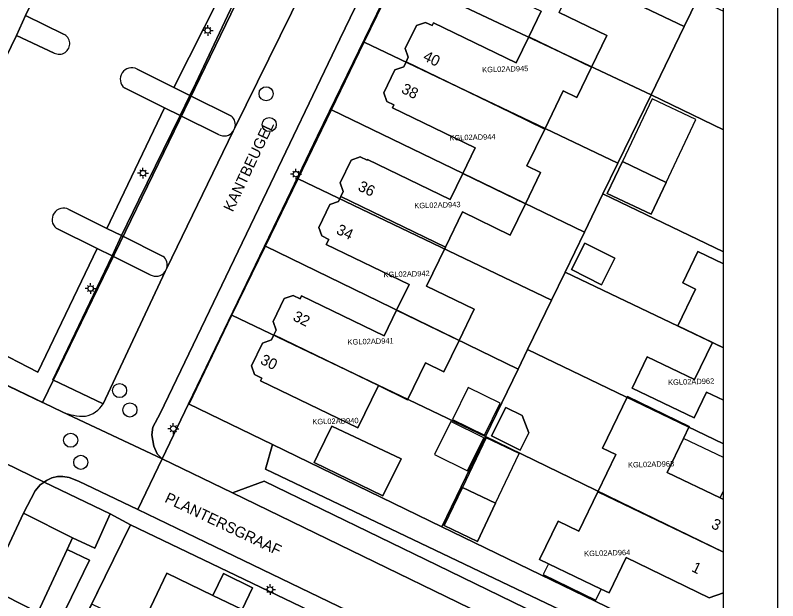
# Model space of a CAD drawing. Extents: x 124901 to 125496, y 515369 to 515789.
# Drawn here: x 125425.6 to 125495.9, y 515463 to 515517 of the extents above; entities that cross this region are included whole.
import ezdxf

# ---------------------------------------------------------------- set-up
doc = ezdxf.new("R2010")
doc.units = 0
for name, color, linetype in [('Alg Kaders', 7, 'Continuous'), ('Gebouw', 7, 'Continuous'), ('Lichtmast', 7, 'Continuous'), ('Luifel', 7, 'Continuous'), ('Onbegroeid terrein', 7, 'Continuous'), ('Parkeren', 7, 'Continuous'), ('Perceelnummers', 7, 'Continuous'), ('Perceelsgrenzen', 7, 'Continuous'), ('Putten', 7, 'Continuous'), ('Teksten', 7, 'Continuous'), ('Vegetatie', 7, 'Continuous'), ('Voetpad', 7, 'Continuous'), ('Wegen lokale weg', 7, 'Continuous')]:
    doc.layers.add(name, color=color, linetype=linetype)

msp = doc.modelspace()

# ---------------------------------------------------------------- linework, layer by layer
at = {"layer": 'Alg Kaders'}
for points in [[(125495.925, 515789.043), (124901.425, 515789.043), (124901.425, 515368.543), (125495.925, 515368.543)], [(125490.925, 515784.043), (124906.425, 515784.043), (124906.425, 515373.543), (125490.925, 515373.543)]]:
    msp.add_lwpolyline(points, close=True, dxfattribs=at)
at = {"layer": 'Gebouw'}
for points in [[(125466.616, 515521.375), (125466.483, 515521.1), (125474.117, 515517.407), (125472.966, 515515.027), (125478.748, 515512.228), (125480.167, 515515.158), (125475.77, 515517.287), (125477.402, 515520.659), (125467.751, 515525.33), (125467.536, 515524.879), (125466.727, 515524.591), (125465.705, 515522.475), (125465.982, 515521.681)], [(125464.052, 515516.076), (125463.437, 515516.373), (125462.603, 515516.082), (125461.581, 515513.966), (125461.863, 515513.175), (125461.648, 515512.723), (125471.299, 515508.051), (125474.434, 515506.533), (125476.135, 515510.047), (125477.397, 515509.436), (125478.748, 515512.228), (125472.966, 515515.027), (125471.814, 515512.647), (125464.18, 515516.34)], [(125460.624, 515511.984), (125459.602, 515509.868), (125459.879, 515509.074), (125460.521, 515508.763), (125460.389, 515508.49), (125468.023, 515504.803), (125466.874, 515502.423), (125472.655, 515499.642), (125474.054, 515502.532), (125472.793, 515503.142), (125474.434, 515506.533), (125471.299, 515508.051), (125461.648, 515512.723), (125461.433, 515512.272)], [(125466.859, 515498.881), (125471.256, 515496.752), (125472.655, 515499.642), (125466.874, 515502.423), (125465.724, 515500.043), (125458.09, 515503.73), (125458.056, 515503.66), (125457.431, 515503.962), (125456.597, 515503.671), (125455.575, 515501.555), (125455.857, 515500.764), (125455.642, 515500.312), (125465.291, 515495.642)], [(125485.644, 515501.614), (125481.598, 515503.528), (125480.209, 515500.592), (125484.255, 515498.678)], [(125455.642, 515500.312), (125455.427, 515499.861), (125454.618, 515499.573), (125453.596, 515497.457), (125453.873, 515496.663), (125454.523, 515496.349), (125454.299, 515495.886), (125461.927, 515492.199), (125460.778, 515489.821), (125466.548, 515487.027), (125467.946, 515489.914), (125463.549, 515492.043), (125465.291, 515495.642)], [(125478.152, 515496.013), (125476.911, 515493.576), (125479.675, 515492.169), (125480.916, 515494.606)], [(125459.628, 515487.443), (125452, 515491.13), (125451.876, 515490.872), (125451.242, 515491.178), (125450.408, 515490.887), (125449.386, 515488.771), (125449.668, 515487.98), (125449.453, 515487.528), (125459.102, 515482.857), (125461.782, 515481.56), (125463.431, 515484.966), (125465.148, 515484.135), (125466.548, 515487.027), (125460.778, 515489.821)], [(125447.684, 515483.879), (125448.349, 515483.558), (125448.22, 515483.29), (125457.21, 515478.95), (125459.102, 515482.857), (125449.453, 515487.528), (125449.238, 515487.077), (125448.429, 515486.789), (125447.407, 515484.673)], [(125472.351, 515480.097), (125470.843, 515480.851), (125469.525, 515478.214), (125472.162, 515476.896), (125472.964, 515478.501)], [(125453.521, 515476.477), (125453.17, 515475.76), (125459.51, 515472.69), (125461.189, 515476.094), (125454.809, 515479.105)], [(125466.853, 515473.459), (125465.176, 515469.949), (125468.229, 515468.489), (125469.907, 515472)], [(125445.38, 515456.564), (125447.8, 515461.59), (125446.54, 515462.199), (125443.839, 515463.505), (125439.61, 515465.55), (125437.183, 515460.514)], [(125446.54, 515462.199), (125447.509, 515464.202), (125444.808, 515465.508), (125443.839, 515463.505)]]:
    msp.add_lwpolyline(points, close=True, dxfattribs=at)
for points in [[(125490.925, 515494.106), (125488.55, 515495.245), (125487.159, 515492.341), (125488.347, 515491.771), (125486.715, 515488.379), (125489.902, 515486.846), (125490.925, 515486.354)], [(125490.925, 515486.354), (125489.902, 515486.846), (125488.264, 515483.428), (125483.891, 515485.525), (125482.503, 515482.63), (125488.22, 515479.89), (125489.362, 515482.266), (125490.925, 515481.515)], [(125490.925, 515472.338), (125490.602, 515472.494), (125485.728, 515474.844), (125487.245, 515477.99), (125487.771, 515479.082), (125482.062, 515481.85), (125479.765, 515477.085), (125480.997, 515476.491), (125479.344, 515473.063), (125490.925, 515467.495)], [(125490.925, 515467.495), (125479.344, 515473.063), (125477.588, 515469.419), (125475.666, 515470.345), (125473.964, 515466.814), (125474.786, 515466.418), (125479.637, 515464.078), (125480.368, 515463.726), (125481.942, 515466.991), (125489.61, 515463.28), (125490.925, 515463.739)]]:
    msp.add_lwpolyline(points, dxfattribs=at)
at = {"layer": 'Lichtmast'}
for p, q in [((125443.363, 515515.931), (125443.363, 515516.131)), ((125443.063, 515515.632), (125442.863, 515515.631)), ((125443.151, 515515.419), (125443.079, 515515.348)), ((125443.151, 515515.843), (125443.081, 515515.914)), ((125443.363, 515515.331), (125443.363, 515515.131)), ((125443.575, 515515.843), (125443.646, 515515.915)), ((125443.575, 515515.419), (125443.645, 515515.348)), ((125443.663, 515515.631), (125443.863, 515515.631)), ((125437.186, 515502.679), (125437.116, 515502.75)), ((125437.398, 515502.767), (125437.398, 515502.967)), ((125437.61, 515502.679), (125437.681, 515502.751)), ((125451.286, 515502.581), (125451.216, 515502.652)), ((125451.498, 515502.669), (125451.498, 515502.869)), ((125451.71, 515502.581), (125451.781, 515502.653)), ((125437.098, 515502.468), (125436.898, 515502.467)), ((125437.186, 515502.255), (125437.114, 515502.184)), ((125437.398, 515502.167), (125437.398, 515501.967)), ((125437.61, 515502.255), (125437.68, 515502.184)), ((125437.698, 515502.467), (125437.898, 515502.467)), ((125451.198, 515502.37), (125450.998, 515502.369)), ((125451.286, 515502.157), (125451.214, 515502.086)), ((125451.498, 515502.069), (125451.498, 515501.869)), ((125451.71, 515502.157), (125451.78, 515502.086)), ((125451.798, 515502.369), (125451.998, 515502.369)), ((125432.354, 515492.03), (125432.284, 515492.101)), ((125432.566, 515492.118), (125432.566, 515492.318)), ((125432.778, 515492.03), (125432.849, 515492.102)), ((125432.266, 515491.819), (125432.066, 515491.818)), ((125432.354, 515491.606), (125432.282, 515491.535)), ((125432.566, 515491.518), (125432.566, 515491.318)), ((125432.778, 515491.606), (125432.848, 515491.535)), ((125432.866, 515491.818), (125433.066, 515491.818)), ((125440.195, 515479.183), (125440.195, 515479.383)), ((125439.895, 515478.884), (125439.695, 515478.883)), ((125439.983, 515478.671), (125439.911, 515478.6)), ((125439.983, 515479.095), (125439.913, 515479.166)), ((125440.407, 515479.095), (125440.478, 515479.167)), ((125440.407, 515478.671), (125440.477, 515478.6)), ((125440.495, 515478.883), (125440.695, 515478.883)), ((125440.195, 515478.583), (125440.195, 515478.383)), ((125448.812, 515464.044), (125448.612, 515464.043)), ((125448.9, 515464.255), (125448.83, 515464.326)), ((125449.112, 515464.343), (125449.112, 515464.543)), ((125449.324, 515464.255), (125449.395, 515464.327)), ((125449.412, 515464.043), (125449.612, 515464.043)), ((125448.9, 515463.831), (125448.828, 515463.76)), ((125449.112, 515463.743), (125449.112, 515463.543)), ((125449.324, 515463.831), (125449.394, 515463.76))]:
    msp.add_line(p, q, dxfattribs=at)
for centre in [(125443.363, 515515.631), (125437.398, 515502.467), (125451.498, 515502.369), (125432.566, 515491.818), (125440.195, 515478.883), (125449.112, 515464.043)]:
    msp.add_circle(centre, 0.25, dxfattribs=at)
at = {"layer": 'Luifel'}
for points in [[(125484.338, 515509.319), (125481.598, 515503.528), (125485.644, 515501.614), (125488.384, 515507.405)], [(125465.94, 515479.736), (125468.875, 515478.292), (125470.319, 515481.226), (125467.384, 515482.67)], [(125465.785, 515479.558), (125464.262, 515476.51), (125467.31, 515474.987), (125468.833, 515478.035)], [(125469.042, 515478.039), (125466.853, 515473.459), (125469.907, 515472), (125472.096, 515476.579)], [(125479.15, 515463.07), (125479.637, 515464.078), (125474.786, 515466.418), (125474.301, 515465.417)]]:
    msp.add_lwpolyline(points, close=True, dxfattribs=at)
msp.add_lwpolyline([(125490.925, 515476.216), (125487.245, 515477.99), (125485.728, 515474.844), (125490.602, 515472.494), (125490.925, 515473.164)], dxfattribs=at)
at = {"layer": 'Onbegroeid terrein'}
for points in [[(125490.925, 515572.93), (125486.902, 515574.852), (125481.271, 515563.266), (125474.678, 515549.593), (125462.223, 515523.884), (125453.501, 515505.907), (125450.658, 515500), (125442.003, 515482.019), (125441.598, 515481.177), (125449.353, 515477.41), (125464.945, 515469.835), (125487.213, 515459.032), (125490.925, 515457.212)], [(125430.976, 515530.884), (125416, 515500), (125410.936, 515489.556), (125412.78, 515488.671), (125413.974, 515490.907), (125418.349, 515500), (125419.408, 515502.202), (125420.273, 515503.939), (125425.747, 515515.155), (125426.577, 515517.021), (125435.435, 515535.182), (125449.018, 515530.602), (125450.733, 515534.132)], [(125442.778, 515524.769), (125448.478, 515522.144), (125452.076, 515529.571), (125449.018, 515530.602), (125435.435, 515535.182), (125426.577, 515517.021), (125430.065, 515515.298)], [(125436.845, 515512.058), (125440.231, 515510.372), (125445.899, 515521.606), (125441.755, 515523.591)], [(125475.77, 515517.287), (125480.167, 515515.158), (125478.748, 515512.228), (125477.397, 515509.436), (125476.135, 515510.047), (125474.434, 515506.533), (125472.793, 515503.142), (125474.054, 515502.532), (125472.655, 515499.642), (125471.256, 515496.752), (125466.859, 515498.881), (125465.291, 515495.642), (125463.549, 515492.043), (125467.946, 515489.914), (125466.548, 515487.027), (125465.148, 515484.135), (125463.431, 515484.966), (125461.782, 515481.56), (125459.102, 515482.857), (125457.21, 515478.95), (125448.22, 515483.29), (125448.349, 515483.558), (125447.684, 515483.879), (125447.407, 515484.673), (125448.429, 515486.789), (125449.238, 515487.077), (125449.453, 515487.528), (125449.668, 515487.98), (125449.386, 515488.771), (125450.408, 515490.887), (125451.242, 515491.178), (125451.876, 515490.872), (125452, 515491.13), (125459.628, 515487.443), (125460.778, 515489.821), (125461.927, 515492.199), (125454.299, 515495.886), (125454.523, 515496.349), (125453.873, 515496.663), (125453.596, 515497.457), (125454.618, 515499.573), (125455.427, 515499.861), (125455.642, 515500.312), (125455.857, 515500.764), (125455.575, 515501.555), (125456.597, 515503.671), (125457.431, 515503.962), (125458.056, 515503.66), (125458.09, 515503.73), (125465.724, 515500.043), (125466.874, 515502.423), (125468.023, 515504.803), (125460.389, 515508.49), (125460.521, 515508.763), (125459.879, 515509.074), (125459.602, 515509.868), (125460.624, 515511.984), (125461.433, 515512.272), (125461.648, 515512.723), (125461.863, 515513.175), (125461.581, 515513.966), (125462.603, 515516.082), (125463.437, 515516.373), (125464.052, 515516.076), (125464.18, 515516.34), (125471.814, 515512.647), (125472.966, 515515.027), (125474.117, 515517.407)], [(125429.216, 515513.547), (125425.747, 515515.155), (125420.273, 515503.939), (125423.856, 515502.228)], [(125435.68, 515510.328), (125439.389, 515508.491), (125440.811, 515507.787), (125441.713, 515509.635), (125440.231, 515510.372), (125436.845, 515512.058)], [(125430.56, 515499.11), (125434.061, 515497.367), (125435.322, 515500), (125439.389, 515508.491), (125435.68, 515510.328)], [(125422.944, 515500.536), (125419.408, 515502.202), (125418.349, 515500), (125413.974, 515490.907), (125423.261, 515486.38), (125423.264, 515486.386), (125427.708, 515484.107), (125433.171, 515495.51), (125429.395, 515497.38)], [(125434.061, 515497.367), (125430.56, 515499.11)], [(125429.395, 515497.38), (125433.171, 515495.51), (125434.563, 515494.821), (125435.405, 515496.698), (125434.061, 515497.367)], [(125490.925, 515481.515), (125489.362, 515482.266), (125488.22, 515479.89), (125482.503, 515482.63), (125483.891, 515485.525), (125488.264, 515483.428), (125489.902, 515486.846), (125486.715, 515488.379), (125488.347, 515491.771), (125487.159, 515492.341), (125488.55, 515495.245), (125490.925, 515494.106)], [(125490.925, 515463.739), (125489.61, 515463.28), (125481.942, 515466.991), (125480.368, 515463.726), (125479.637, 515464.078), (125474.786, 515466.418), (125473.964, 515466.814), (125475.666, 515470.345), (125477.588, 515469.419), (125479.344, 515473.063), (125480.997, 515476.491), (125479.765, 515477.085), (125482.062, 515481.85), (125487.771, 515479.082), (125487.245, 515477.99), (125485.728, 515474.844), (125490.602, 515472.494), (125490.925, 515472.338)], [(125457.218, 515459.955), (125436.24, 515470.006), (125427.701, 515452.562)]]:
    msp.add_lwpolyline(points, dxfattribs=at)
for points in [[(125481.598, 515503.528), (125485.644, 515501.614), (125484.255, 515498.678), (125480.209, 515500.592)], [(125478.152, 515496.013), (125480.916, 515494.606), (125479.675, 515492.169), (125476.911, 515493.576)], [(125472.351, 515480.097), (125472.964, 515478.501), (125472.162, 515476.896), (125469.525, 515478.214), (125470.843, 515480.851)], [(125453.17, 515475.76), (125453.521, 515476.477), (125454.809, 515479.105), (125461.189, 515476.094), (125459.51, 515472.69)], [(125469.907, 515472), (125468.229, 515468.489), (125465.176, 515469.949), (125466.853, 515473.459)], [(125447.8, 515461.59), (125445.38, 515456.564), (125443.043, 515451.71), (125440.706, 515446.855), (125438.285, 515441.827), (125430.08, 515445.77), (125432.506, 515450.805), (125434.845, 515455.659), (125437.183, 515460.514), (125439.61, 515465.55), (125443.839, 515463.505), (125444.808, 515465.508), (125447.509, 515464.202), (125446.54, 515462.199)]]:
    msp.add_lwpolyline(points, close=True, dxfattribs=at)
for centre, radius, start, end in [((125429.67, 515514.408), 0.974, 242.19151, 66.07417), ((125436.347, 515511.136), 1.048, 61.60731, 230.47923), ((125436.347, 515511.136), 1.048, 61.60731, 230.47923), ((125430.062, 515498.188), 1.048, 61.64099, 230.44554), ((125430.062, 515498.188), 1.048, 61.64099, 230.44554)]:
    msp.add_arc(centre, radius, start, end, dxfattribs=at)
at = {"layer": 'Parkeren'}
for points in [[(125451.065, 515519.177), (125447.153, 515521.005), (125445.448, 515517.506), (125442.268, 515510.774), (125441.713, 515509.635), (125445.553, 515507.723)], [(125445.872, 515506.632), (125452.147, 515519.408)], [(125444.347, 515506.035), (125440.811, 515507.787), (125437.015, 515500), (125435.405, 515496.698), (125439.268, 515494.775)], [(125439.59, 515493.693), (125445.722, 515506.327)], [(125438.062, 515493.087), (125434.563, 515494.821), (125429.091, 515483.398), (125433.716, 515481.182), (125439.438, 515493.379)]]:
    msp.add_lwpolyline(points, dxfattribs=at)
for points in [[(125479.548, 515456.488), (125478.49, 515459.49), (125464.507, 515466.302), (125448.564, 515474.053), (125445.638, 515472.977)], [(125430.901, 515468.821), (125426.393, 515471.074), (125423.161, 515464.229), (125427.7, 515461.925), (125430.399, 515467.739)]]:
    msp.add_lwpolyline(points, close=True, dxfattribs=at)
for centre, radius, start, end in [((125444.875, 515506.933), 1.041, 343.22614, 49.37089), ((125444.875, 515506.933), 1.041, 239.54662, 324.43223), ((125438.592, 515493.985), 1.04, 343.70766, 49.43804), ((125438.591, 515493.984), 1.041, 239.49949, 324.46243)]:
    msp.add_arc(centre, radius, start, end, dxfattribs=at)
at = {"layer": 'Perceelsgrenzen'}
for points in [[(125490.925, 515457.207), (125464.945, 515469.835), (125441.643, 515481.155), (125445.603, 515489.346), (125448.69, 515495.731), (125451.695, 515501.947), (125454.769, 515508.305), (125457.788, 515514.55), (125460.796, 515520.771), (125463.885, 515527.161), (125466.909, 515533.415), (125469.979, 515539.764), (125473.42, 515546.88), (125473.912, 515547.898), (125486.939, 515574.835), (125490.925, 515572.929)], [(125371.042, 515509.03), (125394.211, 515497.789), (125397.391, 515499.007), (125406.255, 515494.775), (125407.292, 515491.306), (125428.143, 515481.293), (125438.838, 515503.36), (125447.882, 515522.111), (125445.448, 515523.259), (125464.025, 515561.476)], [(125464.025, 515561.476), (125445.448, 515523.259), (125447.882, 515522.111), (125438.838, 515503.36), (125428.143, 515481.293), (125407.292, 515491.306), (125406.255, 515494.775), (125397.391, 515499.007), (125394.211, 515497.789), (125371.042, 515509.03)], [(125490.925, 515506.445), (125484.24, 515509.693), (125487.285, 515515.984), (125488.528, 515518.553), (125490.925, 515517.398)], [(125490.925, 515495.215), (125479.81, 515500.543), (125481.182, 515503.377), (125484.24, 515509.693), (125490.925, 515506.445)], [(125490.925, 515486.344), (125476.319, 515493.331), (125478.103, 515497.016), (125479.81, 515500.543), (125490.925, 515495.215)], [(125490.925, 515477.49), (125472.866, 515486.198), (125475.068, 515490.747), (125476.319, 515493.331), (125490.925, 515486.344)], [(125490.925, 515467.499), (125482.504, 515471.59), (125468.977, 515478.164), (125471.988, 515484.385), (125472.866, 515486.198), (125490.925, 515477.49)], [(125490.925, 515457.207), (125464.945, 515469.835), (125468.977, 515478.164), (125482.504, 515471.59), (125490.925, 515467.499)]]:
    msp.add_lwpolyline(points, dxfattribs=at)
for points in [[(125463.885, 515527.161), (125466.909, 515533.415), (125490.333, 515522.281), (125488.528, 515518.553), (125487.285, 515515.984)], [(125460.796, 515520.771), (125463.885, 515527.161), (125487.285, 515515.984), (125484.24, 515509.693)], [(125457.788, 515514.55), (125460.796, 515520.771), (125484.24, 515509.693), (125481.182, 515503.377)], [(125454.769, 515508.305), (125457.788, 515514.55), (125481.182, 515503.377), (125479.81, 515500.543), (125478.103, 515497.016)], [(125451.695, 515501.947), (125454.769, 515508.305), (125478.103, 515497.016), (125476.319, 515493.331), (125475.068, 515490.747)], [(125451.695, 515501.947), (125475.068, 515490.747), (125472.866, 515486.198), (125471.988, 515484.385), (125448.69, 515495.731)], [(125445.603, 515489.346), (125448.69, 515495.731), (125471.988, 515484.385), (125468.977, 515478.164)], [(125464.945, 515469.835), (125441.643, 515481.155), (125445.603, 515489.346), (125468.977, 515478.164)], [(125422.352, 515412.077), (125416.323, 515429.095), (125425.515, 515447.977), (125427.947, 515452.971), (125430.307, 515457.819), (125432.68, 515462.693), (125436.24, 515470.006), (125458.379, 515459.386), (125466.196, 515455.636), (125473.945, 515451.919), (125481.696, 515448.201), (125490.418, 515444.017), (125486.87, 515436.73), (125484.12, 515431.04), (125477.96, 515418.22), (125473.069, 515420.579), (125472.365, 515419.12), (125460.158, 515393.807), (125453.949, 515396.807)], [(125458.379, 515459.386), (125454.836, 515452.035), (125432.68, 515462.693), (125436.24, 515470.006)]]:
    msp.add_lwpolyline(points, close=True, dxfattribs=at)
at = {"layer": 'Putten'}
for centre in [(125448.75, 515509.79), (125449.04, 515506.94), (125435.24, 515482.4), (125436.19, 515480.61), (125430.73, 515477.82), (125431.66, 515475.78)]:
    msp.add_circle(centre, 0.65, dxfattribs=at)
at = {"layer": 'Vegetatie'}
for points in [[(125441.755, 515523.591), (125445.899, 515521.606), (125440.231, 515510.372), (125441.713, 515509.635), (125442.268, 515510.774), (125445.448, 515517.506)], [(125426.577, 515517.021), (125425.747, 515515.155), (125429.216, 515513.547)], [(125430.065, 515515.298), (125426.577, 515517.021)], [(125433.716, 515481.182), (125429.091, 515483.398), (125434.563, 515494.821), (125433.171, 515495.51), (125427.708, 515484.107), (125423.264, 515486.386), (125423.261, 515486.38), (125413.974, 515490.907), (125412.78, 515488.671), (125429.95, 515480.425)], [(125490.925, 515457.212), (125487.213, 515459.032), (125485.862, 515455.269), (125481.275, 515457.151), (125479.981, 515460.21), (125448.694, 515475.147), (125449.353, 515477.41), (125441.598, 515481.177), (125439.157, 515476.105), (125445.638, 515472.977), (125448.564, 515474.053), (125464.507, 515466.302), (125478.49, 515459.49), (125479.548, 515456.488), (125489.604, 515451.765), (125490.925, 515454.494)]]:
    msp.add_lwpolyline(points, dxfattribs=at)
for points in [[(125434.061, 515497.367), (125435.405, 515496.698), (125437.015, 515500), (125440.811, 515507.787), (125439.389, 515508.491), (125435.322, 515500)], [(125481.275, 515457.151), (125485.862, 515455.269), (125487.213, 515459.032), (125464.945, 515469.835), (125449.353, 515477.41), (125448.694, 515475.147), (125479.981, 515460.21)], [(125426.393, 515471.074), (125430.901, 515468.821), (125432.945, 515467.846), (125434.362, 515471.036), (125428.28, 515473.943), (125427.913, 515473.706), (125427.454, 515473.161)], [(125421.631, 515460.932), (125426.14, 515458.647), (125426.06, 515458.488), (125428.014, 515457.588), (125432.457, 515466.767), (125430.399, 515467.739), (125427.7, 515461.925), (125423.161, 515464.229)]]:
    msp.add_lwpolyline(points, close=True, dxfattribs=at)
for centre, radius, start, end in [((125429.67, 515514.408), 0.974, 242.19151, 66.07417), ((125431.665, 515482.371), 2.371, 280.52785, 329.90178), ((125431.916, 515485.209), 5.172, 247.65893, 272.01788)]:
    msp.add_arc(centre, radius, start, end, dxfattribs=at)
at = {"layer": 'Voetpad'}
for points in [[(125478.699, 515562.537), (125472.327, 515549.509), (125455.552, 515514.823), (125448.443, 515500), (125438.982, 515480.272), (125438.294, 515479.022), (125438.211, 515478.307), (125438.401, 515477.267), (125438.699, 515476.556), (125439.157, 515476.105), (125441.598, 515481.177), (125442.003, 515482.019), (125450.658, 515500), (125453.501, 515505.907), (125462.223, 515523.884), (125474.678, 515549.593), (125481.271, 515563.266), (125486.902, 515574.852), (125485.145, 515575.722)], [(125457.218, 515459.955), (125458.452, 515459.328), (125475.5, 515451.252), (125486.726, 515445.807), (125487.312, 515447.031), (125471.121, 515454.916), (125443.17, 515468.408), (125436.914, 515471.416), (125431.439, 515474.048), (125430.591, 515474.389), (125430.005, 515474.477), (125429.501, 515474.464), (125429.006, 515474.357), (125428.512, 515474.093), (125428.28, 515473.943), (125434.362, 515471.036), (125436.24, 515470.006)]]:
    msp.add_lwpolyline(points, close=True, dxfattribs=at)
for points in [[(125445.553, 515507.723), (125441.713, 515509.635), (125440.811, 515507.787)], [(125440.811, 515507.787), (125444.347, 515506.035)], [(125445.722, 515506.327), (125445.872, 515506.632)], [(125439.268, 515494.775), (125435.405, 515496.698), (125434.563, 515494.821), (125438.062, 515493.087)], [(125439.438, 515493.379), (125439.59, 515493.693)], [(125427.701, 515452.562), (125436.24, 515470.006), (125434.362, 515471.036), (125432.945, 515467.846), (125430.901, 515468.821), (125430.399, 515467.739), (125432.457, 515466.767), (125428.014, 515457.588)]]:
    msp.add_lwpolyline(points, dxfattribs=at)
for centre, radius, start, end in [((125444.875, 515506.933), 1.041, 343.22614, 49.37089), ((125444.875, 515506.933), 1.041, 239.54662, 324.43223), ((125438.592, 515493.985), 1.04, 343.70766, 49.43804), ((125438.591, 515493.984), 1.041, 239.49949, 324.46243)]:
    msp.add_arc(centre, radius, start, end, dxfattribs=at)
at = {"layer": 'Wegen lokale weg'}
for points in [[(125429.95, 515480.425), (125439.157, 515476.105), (125438.699, 515476.556), (125438.401, 515477.267), (125438.211, 515478.307), (125438.294, 515479.022), (125438.982, 515480.272), (125448.443, 515500), (125455.552, 515514.823), (125472.327, 515549.509), (125468.837, 515559.046), (125470.368, 515562.248), (125476.794, 515575.693), (125477.944, 515578.099), (125478.538, 515579.029), (125479.203, 515579.797), (125479.721, 515580.243), (125479.973, 515580.466)], [(125466.008, 515548.062), (125465.798, 515547.634), (125458.047, 515531.57), (125456.649, 515528.687), (125452.147, 515519.408), (125445.872, 515506.632), (125445.722, 515506.327), (125439.59, 515493.693), (125439.438, 515493.379), (125433.716, 515481.182)], [(125421.631, 515460.932), (125423.161, 515464.229), (125426.393, 515471.074), (125427.454, 515473.161), (125427.913, 515473.706), (125428.28, 515473.943), (125423.349, 515476.349), (125412.318, 515453.738)]]:
    msp.add_lwpolyline(points, dxfattribs=at)
for points in [[(125410.936, 515489.556), (125407.292, 515491.306), (125394.211, 515497.789), (125389.654, 515500), (125378.45, 515505.436), (125376.269, 515500.932), (125424.037, 515477.782), (125423.349, 515476.349), (125428.28, 515473.943), (125428.512, 515474.093), (125429.006, 515474.357), (125429.501, 515474.464), (125430.005, 515474.477), (125430.591, 515474.389), (125431.439, 515474.048), (125436.914, 515471.416), (125439.157, 515476.105), (125429.95, 515480.425), (125412.78, 515488.671)], [(125487.312, 515447.031), (125489.604, 515451.765), (125479.548, 515456.488), (125445.638, 515472.977), (125439.157, 515476.105), (125436.914, 515471.416), (125443.17, 515468.408), (125471.121, 515454.916)]]:
    msp.add_lwpolyline(points, close=True, dxfattribs=at)
for centre, radius, start, end in [((125431.665, 515482.371), 2.371, 280.52785, 329.90178), ((125431.916, 515485.209), 5.172, 247.65893, 272.01788)]:
    msp.add_arc(centre, radius, start, end, dxfattribs=at)

# ---------------------------------------------------------------- texts
at = {"layer": 'Perceelnummers'}
for s, rotation, p in [('KGL02AD945', 1.63534, (125468.678, 515511.755)), ('KGL02AD944', 1.6353, (125465.655, 515505.464)), ('KGL02AD943', 1.63527, (125462.423, 515499.207)), ('KGL02AD942', 1.63523, (125459.58, 515492.847)), ('KGL02AD941', 1.63519, (125456.263, 515486.629)), ('KGL02AD962', 1.63554, (125485.816, 515482.913)), ('KGL02AD940', 1.63515, (125453.021, 515479.272)), ('KGL02AD963', 1.6355, (125482.122, 515475.29)), ('KGL02AD964', 1.63545, (125478.078, 515467.108))]:
    msp.add_text(s, height=0.5, rotation=rotation, dxfattribs=at).set_placement(p)
at = {"layer": 'Teksten'}
for s, rotation, p in [('40', 334.2, (125463.138, 515512.913)), ('38', 334.2, (125461.138, 515509.913)), ('KANTBEUGEL', 64.7, (125445.672, 515498.821)), ('36', 334.2, (125457.138, 515500.913)), ('34', 334.2, (125455.138, 515496.913)), ('32', 334.2, (125451.138, 515488.913)), ('30', 334.2, (125448.138, 515484.913)), ('PLANTERSGRAAF', 334.6, (125439.321, 515472.145)), ('3', 334.3, (125489.709, 515469.761)), ('1', 334.2, (125487.902, 515465.762))]:
    msp.add_text(s, height=1, rotation=rotation, dxfattribs=at).set_placement(p)

doc.saveas('drawing.dxf')
